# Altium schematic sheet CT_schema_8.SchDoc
size 308 x 210 mm
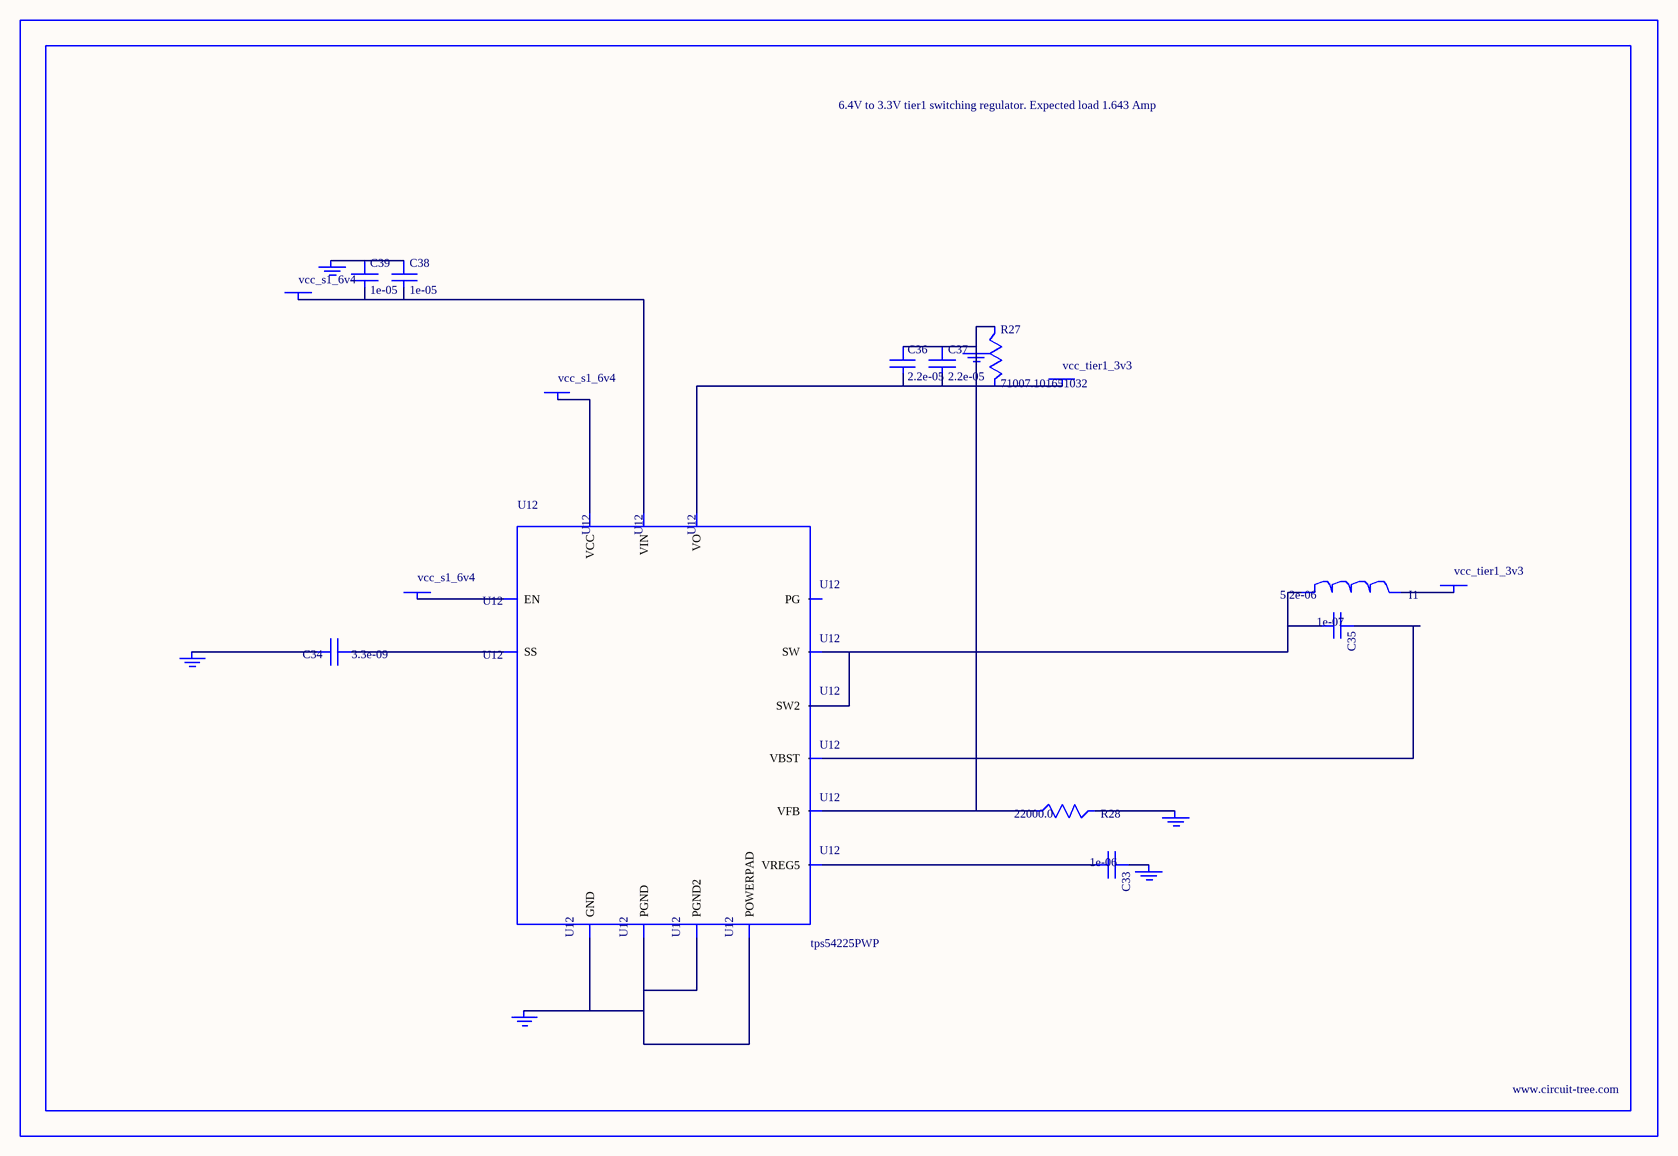
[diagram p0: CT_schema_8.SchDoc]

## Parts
BORDER7  (no value)
C33  1e-06  [C0603]
C34  3.3e-09  [C0402]
C35  1e-07  [C0402]
C36  2.2e-05  [C1210]
C37  2.2e-05  [C1210]
C38  1e-05  [C0805]
C39  1e-05  [C0805]
GND_INSTANCE_7_0  (no value)
GND_INSTANCE_7_1  (no value)
GND_INSTANCE_7_2  (no value)
GND_INSTANCE_7_3  (no value)
GND_INSTANCE_7_4  (no value)
GND_INSTANCE_7_5  (no value)
I1  5.2e-06  [DR1040]
POWER_INSTANCE_7_0  vcc_tier1_3v3
POWER_INSTANCE_7_1  vcc_s1_6v4
POWER_INSTANCE_7_2  vcc_tier1_3v3
POWER_INSTANCE_7_3  vcc_s1_6v4
POWER_INSTANCE_7_4  vcc_s1_6v4
R27  71007.101651032  [R0603]
R28  22000.0  [R0603]
U12  tps54225PWP  [HTSSOP14]

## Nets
NetC33_1: C33.1 GND_INSTANCE_7_2.0(GND)
NetC33_2: C33.2 U12.3(VREG5)
NetC34_1: C34.1 U12.4(SS)
NetC34_2: C34.2 GND_INSTANCE_7_3.0(GND)
NetC35_1: C35.1 U12.12(VBST)
NetC35_2: C35.2 I1.1 U12.10(SW) U12.11(SW2)
NetC36_1: C36.1 C37.1 GND_INSTANCE_7_0.0(GND) R27.1 R28.1 U12.2(VFB)
NetC36_2: C36.2 C37.2 POWER_INSTANCE_7_0.0(PWR) R27.2 U12.1(VO)
NetC38_1: C38.1 C39.1 GND_INSTANCE_7_5.0(GND)
NetC38_2: C38.2 C39.2 POWER_INSTANCE_7_3.0(PWR) U12.13(VIN)
NetGND_INSTANCE_7_1_0: GND_INSTANCE_7_1.0(GND) R28.2
NetGND_INSTANCE_7_4_0: GND_INSTANCE_7_4.0(GND) U12.5(GND) U12.8(PGND) U12.9(PGND2) U12.15(POWERPAD)
NetI1_2: I1.2 POWER_INSTANCE_7_2.0(PWR)
NetPOWER_INSTANCE_7_1_0: POWER_INSTANCE_7_1.0(PWR) U12.7(EN)
NetPOWER_INSTANCE_7_4_0: POWER_INSTANCE_7_4.0(PWR) U12.14(VCC)

Not connected (* = marked no-connect by the designer): U12 6(PG)

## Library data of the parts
BORDER7 = BORDER_PAGE7
C33 = C0603C105K3RACTU
C34 = C0402C332K3RAC
C35 = C0402C104K3RACTU
C36 C37 = GRM32ER61E226ME15L
C38 C39 = C0805C106K8RACTU
GND_INSTANCE_7_0-GND_INSTANCE_7_5 = GND
I1 = DR1040-5R2-R
POWER_INSTANCE_7_0-POWER_INSTANCE_7_4 = PWR
R27 = R27
R28 = RC0603JR-0722KL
